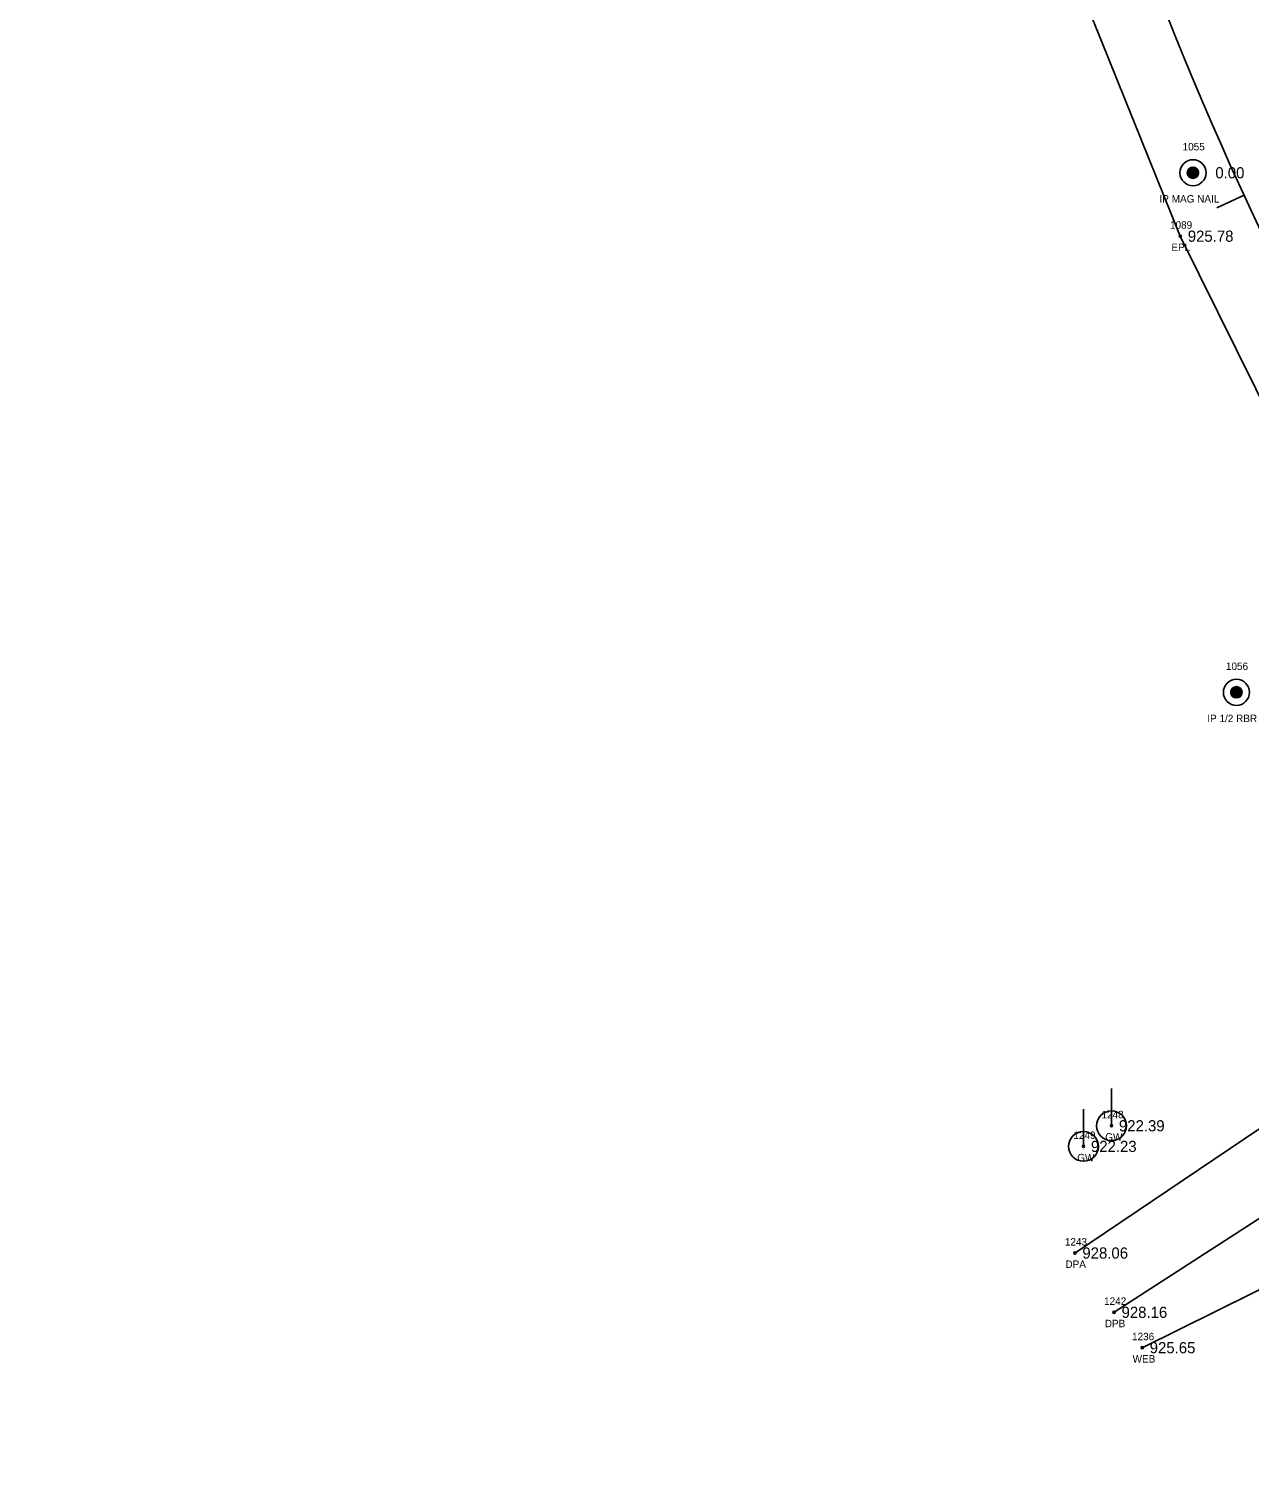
# Model space of a CAD drawing. Extents: x 1528109 to 1531398, y 1157799 to 1162548.
# Drawn here: x 1529769.5 to 1529933.4, y 1159266.8 to 1159461.9 of the extents above; entities that cross this region are included whole.
import ezdxf

# ---------------------------------------------------------------- set-up
doc = ezdxf.new("R2010")
doc.units = 0
for name, color, linetype in [('RD_EX_Driveway', 7, 'Continuous'), ('RD_EX_Driveway_txCode', 7, 'Continuous'), ('RD_EX_DV_Prop_txCode', 7, 'Continuous'), ('RD_EX_DV_PropPin', 7, 'Continuous'), ('RD_EX_H2O', 7, 'Continuous'), ('RD_EX_H2O_txCode', 7, 'Continuous'), ('RD_EX_Road', 7, 'Continuous'), ('RD_EX_Road_txCode', 7, 'Continuous'), ('RD_EX_TX_Driveway_ELEV', 7, 'Continuous'), ('RD_EX_TX_DV_Prop_ELEV', 7, 'Continuous'), ('RD_EX_TX_H2O_ELEV', 7, 'Continuous'), ('RD_EX_TX_Road_ELEV', 7, 'Continuous'), ('RD_EX_TX_UT_ELEV', 7, 'Continuous'), ('RD_EX_UT', 7, 'Continuous'), ('RD_EX_UT_txCode', 7, 'Continuous'), ('RD_HC_Cl', 7, 'Continuous'), ('RD_HC_Data_Tic', 7, 'Continuous'), ('RD_SMD_Locator', 7, 'Continuous')]:
    doc.layers.add(name, color=color, linetype=linetype)

msp = doc.modelspace()

# ---------------------------------------------------------------- linework, layer by layer
at = {"layer": 'RD_EX_Driveway'}
for points in [[(1529909.91, 1159297.62), (1529941.05, 1159318.59), (1529954.36, 1159331.55), (1529963.43, 1159347.55), (1529963.99, 1159359.24), (1529961.59, 1159366.88)], [(1530005.21, 1159311.5), (1529996.29, 1159318.73), (1529990.79, 1159321.06), (1529971.78, 1159321.49), (1529956.32, 1159316.25), (1529915.17, 1159289.66)]]:
    msp.add_lwpolyline(points, dxfattribs=at)
at = {"layer": 'RD_EX_DV_PropPin'}
for p, q in [((1529925.02, 1159442.42), (1529925.02, 1159442.81)), ((1529925.06, 1159442.32), (1529925.06, 1159442.92)), ((1529925.09, 1159442.25), (1529925.09, 1159442.99)), ((1529925.13, 1159442.19), (1529925.13, 1159443.04)), ((1529925.16, 1159442.14), (1529925.16, 1159443.09)), ((1529925.2, 1159442.1), (1529925.2, 1159443.13)), ((1529925.23, 1159442.07), (1529925.23, 1159443.17)), ((1529925.27, 1159442.04), (1529925.27, 1159443.2)), ((1529925.3, 1159442.01), (1529925.3, 1159443.23)), ((1529925.34, 1159441.98), (1529925.34, 1159443.25)), ((1529925.37, 1159441.96), (1529925.37, 1159443.27)), ((1529925.41, 1159441.94), (1529925.41, 1159443.29)), ((1529925.44, 1159441.92), (1529925.44, 1159443.31)), ((1529925.48, 1159441.91), (1529925.48, 1159443.33)), ((1529925.51, 1159441.9), (1529925.51, 1159443.34)), ((1529925.55, 1159441.89), (1529925.55, 1159443.35)), ((1529925.58, 1159441.88), (1529925.58, 1159443.36)), ((1529925.62, 1159441.87), (1529925.62, 1159443.37)), ((1529925.65, 1159441.86), (1529925.65, 1159443.37)), ((1529925.69, 1159441.86), (1529925.69, 1159443.38)), ((1529925.72, 1159441.86), (1529925.72, 1159443.38)), ((1529925.76, 1159441.86), (1529925.76, 1159443.38)), ((1529925.79, 1159441.86), (1529925.79, 1159443.38)), ((1529925.83, 1159441.86), (1529925.83, 1159443.38)), ((1529925.86, 1159441.86), (1529925.86, 1159443.37)), ((1529925.9, 1159441.87), (1529925.9, 1159443.37)), ((1529925.93, 1159441.88), (1529925.93, 1159443.36)), ((1529925.97, 1159441.89), (1529925.97, 1159443.35)), ((1529926, 1159441.9), (1529926, 1159443.34)), ((1529926.04, 1159441.91), (1529926.04, 1159443.33)), ((1529926.07, 1159441.92), (1529926.07, 1159443.31)), ((1529926.11, 1159441.94), (1529926.11, 1159443.29)), ((1529926.14, 1159441.96), (1529926.14, 1159443.27)), ((1529926.18, 1159441.98), (1529926.18, 1159443.25)), ((1529926.21, 1159442.01), (1529926.21, 1159443.23)), ((1529926.25, 1159442.04), (1529926.25, 1159443.2)), ((1529926.28, 1159442.07), (1529926.28, 1159443.17)), ((1529926.32, 1159442.1), (1529926.32, 1159443.13)), ((1529926.35, 1159442.14), (1529926.35, 1159443.09)), ((1529926.39, 1159442.19), (1529926.39, 1159443.04)), ((1529926.42, 1159442.25), (1529926.42, 1159442.99)), ((1529926.46, 1159442.32), (1529926.46, 1159442.92)), ((1529926.49, 1159442.42), (1529926.49, 1159442.81)), ((1529930.85, 1159372.68), (1529930.85, 1159373.07)), ((1529930.89, 1159372.58), (1529930.89, 1159373.17)), ((1529930.92, 1159372.51), (1529930.92, 1159373.25)), ((1529930.96, 1159372.45), (1529930.96, 1159373.3)), ((1529930.99, 1159372.4), (1529930.99, 1159373.35)), ((1529931.03, 1159372.36), (1529931.03, 1159373.39)), ((1529931.06, 1159372.33), (1529931.06, 1159373.43)), ((1529931.1, 1159372.29), (1529931.1, 1159373.46)), ((1529931.13, 1159372.27), (1529931.13, 1159373.49)), ((1529931.17, 1159372.24), (1529931.17, 1159373.51)), ((1529931.2, 1159372.22), (1529931.2, 1159373.53)), ((1529931.24, 1159372.2), (1529931.24, 1159373.55)), ((1529931.27, 1159372.18), (1529931.27, 1159373.57)), ((1529931.31, 1159372.17), (1529931.31, 1159373.58)), ((1529931.34, 1159372.16), (1529931.34, 1159373.6)), ((1529931.38, 1159372.14), (1529931.38, 1159373.61)), ((1529931.41, 1159372.14), (1529931.41, 1159373.62)), ((1529931.45, 1159372.13), (1529931.45, 1159373.62)), ((1529931.48, 1159372.12), (1529931.48, 1159373.63)), ((1529931.52, 1159372.12), (1529931.52, 1159373.63)), ((1529931.55, 1159372.12), (1529931.55, 1159373.64)), ((1529931.59, 1159372.11), (1529931.59, 1159373.64)), ((1529931.62, 1159372.12), (1529931.62, 1159373.64)), ((1529931.66, 1159372.12), (1529931.66, 1159373.63)), ((1529931.69, 1159372.12), (1529931.69, 1159373.63)), ((1529931.73, 1159372.13), (1529931.73, 1159373.62)), ((1529931.76, 1159372.14), (1529931.76, 1159373.62)), ((1529931.8, 1159372.14), (1529931.8, 1159373.61)), ((1529931.83, 1159372.16), (1529931.83, 1159373.6)), ((1529931.87, 1159372.17), (1529931.87, 1159373.58)), ((1529931.9, 1159372.18), (1529931.9, 1159373.57)), ((1529931.94, 1159372.2), (1529931.94, 1159373.55)), ((1529931.97, 1159372.22), (1529931.97, 1159373.53)), ((1529932.01, 1159372.24), (1529932.01, 1159373.51)), ((1529932.04, 1159372.27), (1529932.04, 1159373.49)), ((1529932.08, 1159372.29), (1529932.08, 1159373.46)), ((1529932.11, 1159372.33), (1529932.11, 1159373.43)), ((1529932.15, 1159372.36), (1529932.15, 1159373.39)), ((1529932.18, 1159372.4), (1529932.18, 1159373.35)), ((1529932.22, 1159372.45), (1529932.22, 1159373.3)), ((1529932.25, 1159372.51), (1529932.25, 1159373.25)), ((1529932.29, 1159372.58), (1529932.29, 1159373.17)), ((1529932.32, 1159372.68), (1529932.32, 1159373.07))]:
    msp.add_line(p, q, dxfattribs=at)
for centre, radius in [((1529925.76, 1159442.62), 1.75), ((1529925.76, 1159442.62), 0.761), ((1529931.59, 1159372.88), 1.75), ((1529931.59, 1159372.88), 0.761)]:
    msp.add_circle(centre, radius, dxfattribs=at)
at = {"layer": 'RD_EX_H2O'}
msp.add_lwpolyline([(1530046.75, 1159214.57), (1530022.58, 1159243.79), (1530014.7, 1159242.9), (1530019.04, 1159253.45), (1530004.76, 1159269.6), (1529985.6, 1159289.95), (1529959.08, 1159302.6), (1529953.51, 1159302.02), (1529918.95, 1159284.91)], dxfattribs=at)
at = {"layer": 'RD_EX_Road'}
msp.add_lwpolyline([(1530332.28, 1159136.67), (1530288.96, 1159147.06), (1530245.68, 1159158), (1530197.52, 1159172.18), (1530159.1, 1159186.57), (1530108.6, 1159214.89), (1530072.67, 1159242.37), (1530037.12, 1159276.96), (1530005.21, 1159311.5), (1529961.59, 1159366.88), (1529941.79, 1159398.29), (1529924.06, 1159434.11), (1529903.77, 1159484.39), (1529891.44, 1159520.8), (1529876.79, 1159564.7), (1529862.9, 1159606.82), (1529836.94, 1159684.29), (1529820.66, 1159733.09), (1529800.02, 1159794.4), (1529769.54, 1159884.46)], dxfattribs=at)
at = {"layer": 'RD_EX_UT'}
for p, q in [((1529914.82, 1159314.7), (1529914.82, 1159319.7)), ((1529911.06, 1159311.93), (1529911.06, 1159316.93))]:
    msp.add_line(p, q, dxfattribs=at)
for centre in [(1529914.82, 1159314.7), (1529911.06, 1159311.93)]:
    msp.add_circle(centre, 2, dxfattribs=at)
at = {"layer": 'RD_HC_Cl'}
msp.add_arc((1530368.9, 1159640.71), 480.41, 198.568, 222.8065, dxfattribs=at)
at = {"layer": 'RD_HC_Data_Tic'}
msp.add_line((1529932.61, 1159439.6), (1529928.98, 1159437.92), dxfattribs=at)
at = {"layer": 'RD_SMD_Locator'}
for centre in [(1529925.76, 1159442.62), (1529924.06, 1159434.11), (1529931.59, 1159372.88), (1529914.82, 1159314.7), (1529911.06, 1159311.93), (1529909.91, 1159297.62), (1529915.17, 1159289.66), (1529918.95, 1159284.91)]:
    msp.add_circle(centre, 0.15, dxfattribs=at)

# ---------------------------------------------------------------- texts
at = {"layer": 'RD_EX_Driveway_txCode'}
for s, p in [('1243', (1529908.56, 1159298.62)), ('DPA', (1529908.64, 1159295.62)), ('1242', (1529913.83, 1159290.66)), ('DPB', (1529913.92, 1159287.66))]:
    msp.add_text(s, height=1, dxfattribs=at).set_placement(p)
at = {"layer": 'RD_EX_DV_Prop_txCode'}
for s, p in [('1055', (1529924.37, 1159445.62)), ('IP MAG NAIL', (1529921.27, 1159438.62)), ('1056', (1529930.18, 1159375.88)), ('IP 1/2 RBR', (1529927.68, 1159368.88))]:
    msp.add_text(s, height=1, dxfattribs=at).set_placement(p)
at = {"layer": 'RD_EX_H2O_txCode'}
for s, p in [('1236', (1529917.58, 1159285.91)), ('WEB', (1529917.66, 1159282.91))]:
    msp.add_text(s, height=1, dxfattribs=at).set_placement(p)
at = {"layer": 'RD_EX_Road_txCode'}
for s, p in [('1089', (1529922.68, 1159435.11)), ('EPL', (1529922.86, 1159432.11))]:
    msp.add_text(s, height=1, dxfattribs=at).set_placement(p)
at = {"layer": 'RD_EX_TX_Driveway_ELEV'}
for s, p in [('928.06', (1529910.91, 1159296.87)), ('928.16', (1529916.17, 1159288.91))]:
    msp.add_text(s, height=1.5, dxfattribs=at).set_placement(p)
at = {"layer": 'RD_EX_TX_DV_Prop_ELEV'}
msp.add_text('0.00', height=1.5, dxfattribs=at).set_placement((1529928.76, 1159441.87))
at = {"layer": 'RD_EX_TX_H2O_ELEV'}
msp.add_text('925.65', height=1.5, dxfattribs=at).set_placement((1529919.95, 1159284.16))
at = {"layer": 'RD_EX_TX_Road_ELEV'}
msp.add_text('925.78', height=1.5, dxfattribs=at).set_placement((1529925.06, 1159433.36))
at = {"layer": 'RD_EX_TX_UT_ELEV'}
for s, p in [('922.39', (1529915.82, 1159313.95)), ('922.23', (1529912.06, 1159311.18))]:
    msp.add_text(s, height=1.5, dxfattribs=at).set_placement(p)
at = {"layer": 'RD_EX_UT_txCode'}
for s, p in [('1248', (1529913.48, 1159315.7)), ('1249', (1529909.71, 1159312.93)), ('GW', (1529913.98, 1159312.7)), ('GW', (1529910.22, 1159309.93))]:
    msp.add_text(s, height=1, dxfattribs=at).set_placement(p)

doc.saveas('drawing.dxf')
